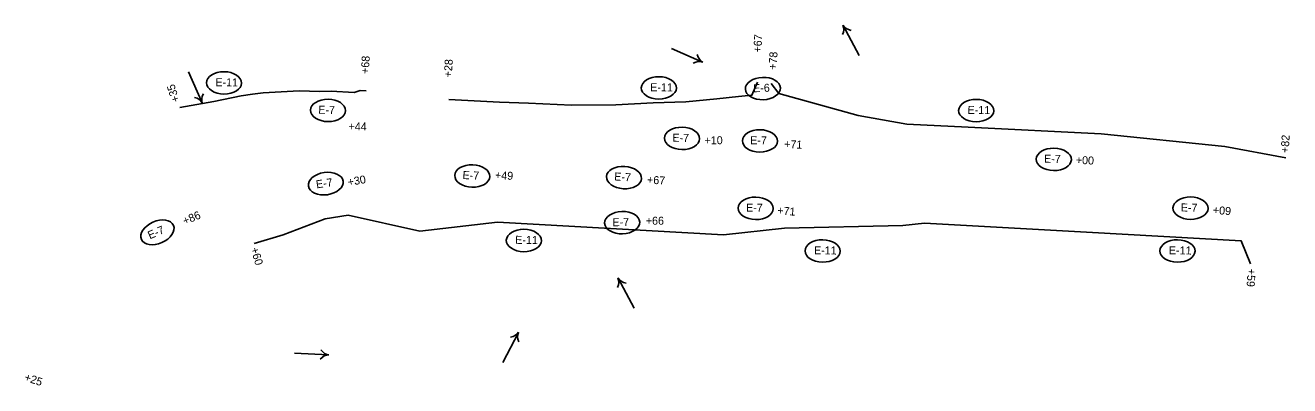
# Model space of a CAD drawing. Extents: x 669236 to 673912, y 735758 to 754788.
# Drawn here: x 672585 to 673572, y 753154 to 753436 of the extents above; entities that cross this region are included whole.
import ezdxf

# ---------------------------------------------------------------- set-up
doc = ezdxf.new("R2010")
doc.units = 0
for name, color, linetype in [('R_Erosion_2', 7, 'Continuous'), ('R_Erosion_3', 7, 'Continuous'), ('R_Flow Arrows', 7, 'Continuous')]:
    doc.layers.add(name, color=color, linetype=linetype)

msp = doc.modelspace()

# ---------------------------------------------------------------- linework, layer by layer
at = {"layer": 'R_Erosion_2'}
msp.add_line((673177.94, 753277.64), (673177.94, 753277.64), dxfattribs=at)
at = {"layer": 'R_Erosion_3'}
for points in [[(672705.67, 753372.09), (672732.15, 753376.58), (672753.56, 753381.02), (672762.5, 753382.49), (672770.75, 753383.4), (672798.89, 753385), (672814.99, 753384.55), (672823.97, 753384.7), (672841.74, 753383.71), (672846.59, 753385.2), (672851.18, 753385.05)], [(672915.86, 753378.35), (672955.25, 753376.24), (672977.92, 753375.26), (673011.55, 753373.8), (673046.18, 753374.07), (673075.38, 753375.62), (673100.84, 753376.45), (673125.15, 753378.84), (673142.02, 753380.5), (673152.42, 753381.53), (673156.87, 753391.67)], [(673569.45, 753332.63), (673521.73, 753341.56), (673425.25, 753351.31), (673321.43, 753356.59), (673273.51, 753359.03), (673235.31, 753365.81), (673173.37, 753382.97), (673167.48, 753390.72)], [(672893.21, 753275.19), (672837.15, 753287.7), (672819.11, 753284.88), (672786.47, 753272.43), (672763.8, 753265.79)], [(672893.21, 753275.19), (672953.69, 753282.35), (673130.31, 753272.39), (673177.94, 753277.64), (673270.24, 753279.74)], [(673270.24, 753279.74), (673287.35, 753281.65), (673413.67, 753274.53), (673534.59, 753267.7), (673541.77, 753249.74)]]:
    msp.add_lwpolyline(points, dxfattribs=at)
for centre, major_axis in [((672740.22, 753391.23), (13.7, -0.16)), ((673079.78, 753387.31), (13.7, -0.16)), ((673161.03, 753386.82), (13.69, 0.52)), ((672821.42, 753369.7), (13.7, -0.16)), ((673327.6, 753369.59), (13.7, -0.16)), ((673097.92, 753347.83), (13.7, -0.24)), ((673158.7, 753345.86), (13.7, -0.16)), ((673388.2, 753331.41), (13.7, -0.24)), ((672934.08, 753318.44), (13.69, -0.5)), ((673052.55, 753317.22), (13.67, -0.83)), ((672819.63, 753312.47), (13.55, 1.98)), ((673155.42, 753293.15), (13.7, -0.16)), ((673494.97, 753293.27), (13.7, -0.24)), ((672688.18, 753274.36), (12.54, 5.5)), ((673051.15, 753281.98), (13.69, 0.45)), ((672974.36, 753268.02), (13.7, -0.16)), ((673207.65, 753259.83), (13.7, -0.16)), ((673484.79, 753259.83), (13.7, -0.16))]:
    msp.add_ellipse(centre, major_axis=major_axis, ratio=0.638788, dxfattribs=at)
at = {"layer": 'R_Flow Arrows'}
for p, q in [((673223.64, 753436.13), (673236.13, 753412.68)), ((673113.87, 753407.44), (673089.57, 753418.15)), ((672723.1, 753375.55), (672712.57, 753399.94)), ((673047.95, 753238.54), (673060.44, 753215.1)), ((672970.09, 753196.21), (672957.81, 753172.66)), ((672821.89, 753178.58), (672795.36, 753179.94))]:
    msp.add_line(p, q, dxfattribs=at)
for centre, major_axis, start_param, end_param in [((673205.65, 753427.04), (17.79, 9.48), 5.662936, 6.259934), ((673241.31, 753445.83), (-17.79, -9.48), 0.023252, 0.620249), ((673105.99, 753388.89), (8.13, 18.45), 0.023252, 0.620249), ((673122.4, 753425.71), (-8.13, -18.45), 5.662936, 6.259934), ((672704.7, 753367.32), (18.51, 7.99), 0.023252, 0.620249), ((672741.78, 753383.14), (-18.51, -7.99), 5.662936, 6.259934), ((673029.95, 753229.45), (17.79, 9.48), 5.662936, 6.259934), ((673065.62, 753248.25), (-17.79, -9.48), 0.023252, 0.620249), ((672952.42, 753205.92), (17.88, -9.32), 5.662936, 6.259934), ((672988.08, 753187.12), (-17.88, 9.32), 0.023252, 0.620249), ((672821.13, 753158.44), (1.03, 20.14), 0.023252, 0.620249), ((672823.35, 753198.69), (-1.03, -20.14), 5.662936, 6.259934)]:
    msp.add_ellipse(centre, major_axis=major_axis, ratio=0.5625, start_param=start_param, end_param=end_param, dxfattribs=at)

# ---------------------------------------------------------------- texts
at = {"layer": 'R_Erosion_3'}
for s, rotation, p in [('+67', 86.37073, (673159.7, 753414.84)), ('+78', 86.37073, (673171.62, 753401.28)), ('+68', 86.37073, (672853.18, 753398.04)), ('+28', 86.37073, (672918, 753395.41)), ('E-11', 359.3421, (672733.47, 753388.64)), ('+35', 108.0546, (672705.66, 753377.32)), ('E-11', 359.3421, (673073.02, 753384.73)), ('E-6', 2.18617, (673153.5, 753383.87)), ('E-7', 359.3421, (672813.8, 753367.12)), ('E-11', 359.3421, (673320.85, 753367)), ('+44', 360, (672837.45, 753354.01)), ('E-7', 359.00782, (673090.29, 753345.29)), ('E-7', 359.3421, (673151.09, 753343.28)), ('+71', 357.437, (673177.54, 753340.35)), ('+82', 86.37073, (673571.56, 753336.28)), ('E-7', 359.00782, (673380.57, 753328.88)), ('+00', 357.309, (673405.27, 753327.98)), ('E-7', 8.31463, (672812.51, 753308.74)), ('+30', 9.903, (672837.39, 753310.51)), ('E-7', 357.9052, (672926.4, 753316.06)), ('+49', 356.554, (672951.66, 753316.18)), ('E-7', 356.51653, (673044.82, 753315.02)), ('+67', 356.879, (673070.42, 753312.49)), ('E-7', 359.3421, (673147.81, 753290.58)), ('E-7', 359.00782, (673487.34, 753290.74)), ('+86', 22.681, (672709.53, 753280.11)), ('E-7', 1.88146, (673043.66, 753279.07)), ('+71', 355.239, (673172.11, 753288.53)), ('+09', 356.114, (673512.27, 753288.79)), ('E-7', 23.67077, (672682.3, 753268.88)), ('E-11', 359.3421, (672967.6, 753265.43)), ('+60', 285.79342, (672760.99, 753261.73)), ('E-11', 359.3421, (673200.9, 753257.25)), ('E-11', 359.3421, (673478.04, 753257.25)), ('+59', 266.28508, (673539.66, 753246.09)), ('+25', 341.49257, (672583.77, 753158.59))]:
    msp.add_text(s, height=6.25, rotation=rotation, dxfattribs=at).set_placement(p)
for s, p in [('+10', (673115.46, 753343.26)), ('+66', (673069.58, 753280.35))]:
    msp.add_text(s, height=6.25, dxfattribs=at).set_placement(p)

doc.saveas('drawing.dxf')
